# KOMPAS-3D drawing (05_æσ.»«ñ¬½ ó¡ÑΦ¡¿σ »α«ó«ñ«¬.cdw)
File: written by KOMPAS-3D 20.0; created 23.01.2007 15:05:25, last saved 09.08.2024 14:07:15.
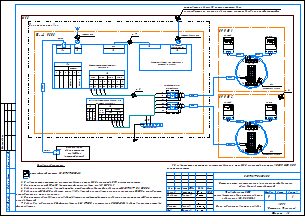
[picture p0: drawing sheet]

Sheet 1: A3, landscape

Document properties: Автор: Лескин; Организация: ЗАО ИТФ "СИСТЕМЫ И ТЕХНОЛОГИИ"; Разработал: Антошин; Проверил: Тарасов; Утвердил: Шмончев; Н. контр.: Силаков; Количество листов документа: 1; Полное имя файла: \\s-tech\depts\Отдел_ПКО\Проекты\Типовые проекты МКД 2023\!Типовой проект\2_Типовой проект МКД_Радиоканал\05_Сх.подкл внешних проводок.cdw

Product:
- Part/product: (unnamed)
  - Component: \\Helios\отдел_пко\Общая папка Компас\_Addons\Signatures\Signatures.lfr|Тарасов  | Полное имя файла: C:\Users\MAntoshin\AppData\Local\Temp\qlkzkl.frw; source file: \\s-tech\depts\Отдел_ПКО\Проекты\Program Files\ASCON\KOMPAS-3D V13\Libs\_Addons\Signatures\Signatures.lfr
  - Component: \\Helios\отдел_пко\Общая папка Компас\_Addons\Signatures\Signatures.lfr|Силаков  | Полное имя файла: C:\Users\MAntoshin\AppData\Local\Temp\eiczbt.frw; source file: \\s-tech\depts\Отдел_ПКО\Проекты\Program Files\ASCON\KOMPAS-3D V13\Libs\_Addons\Signatures\Signatures.lfr
  - Component: \\Helios\отдел_пко\Общая папка Компас\_Addons\Signatures\Signatures.lfr|Шмончев  | Полное имя файла: C:\Users\MAntoshin\AppData\Local\Temp\hsklda.frw; source file: \\s-tech\depts\Отдел_ПКО\Проекты\Program Files\ASCON\KOMPAS-3D V13\Libs\_Addons\Signatures\Signatures.lfr

Title block, sheet 1: designation: ВЛСТ 1277.02.002 С5; Количество листов документа: 3; organisation: АО ГК / "Системы и Технологии"; Форматы листов документа: A3; stored path: C:\Program Files\ASCON\KOMPAS-3D V8 Plus\Templates\Чертеж строительный зданий и сооружений.cdt; cell 302: Система учета электроэнергии (с организацией удаленного / сбора данных) потребителей; cell 303: Типовой проект ИСУЭ / многоквартирного дома с использованием / радиоканала (F2/868 МГц); cell 304: Схема электрическая однолинейная; cell 320: Р

Referenced files in \\Helios\отдел_пко\Общая папка Компас\_Addons\Signatures\: Signatures.lfr|Тарасов, Signatures.lfr, Signatures.lfr|Силаков, Signatures.lfr|Шмончев
Referenced files: qlkzkl.frw, eiczbt.frw, hsklda.frw
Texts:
  Тарасов
  Силаков
  Шмончев
  Normal
  Body Text,Письмо в Интернет,body text
  TXT
  Centerline
  Outline
  присоединением к шине заземления.
  производителей.
  формирователя.
  RF-формирователь Link ST200.F2-K1
  (ВЛСТ 339.10.000-K1)
  Питание
  COM1
  COM2
  COM3
  COM4
  USB
  GSM
  Интеллектуальный контроллер
  SM160-02М
  Ethernet
  Электрощитовая
  Шкаф УСПД
  МКД
  Оборудование
  связи интернет
  провайдера
  (существующее)
  Антенна GSM
  Шина заземления
  Клеммный блок для
  цепей RS-485
  Антенна RF-868 МГц
  RF антенна
  (разъем SMA-F)
  ВРУ №1
  Сч. ОДПУ
  Сч. МОП
  ПРК
  ВЛСТ 215.00.000-04
  ВРУ №2
  может изменяться.
  - трехфазный счетчик КВАНТ ST2000-12.
  RJ-45
  Преобразователь линии RS-485/CAN
  (ВЛСТ 217.00.000-04)
  CAN
  RS-485
  out
  установить не ближе 1.5 метра от стены дома
  рекомендуется на плоскую поверхность крыши подъезда или иной пристройки
  POLYLINE_STYLE_0.09_RGB_0_0_0
  POLYLINE_STYLE_0.18_RGB_0_0_0
  POLYLINE_STYLE_0.09_RGB_0_0_255
  Черная основная
  Красная штриховая
  сплошная своя 0,54 мм на бумаге
  Красная основная
  CONTINUOUS0
  POLYLINE_STYLE_0.18_RGB_255_0_0
  CONTINUOUS_RGB_0_0_0_THICK_0.25
  Стили документа
  Разраб.
  Н.контр.
  Утв.
  Антошин
  Схема подключения внешних проводок
  03 Рабочие чертежи основного комплекта. ГОСТ Р 21.1101-2009 Ф3
Dimensions and other numbers on the sheet: 1,8; 2,5; 1; 2; 3; 4; 5; 6; +10..30 В; -10..30 В; 8; 7; 1.1; 1.2; 2.3; 2.4; 2.1; 2.2; 1.10; 2.10; +10...30 В; 4  5   6; -10...30 В; 5 В; 100 мА; 24; 25; 10.21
